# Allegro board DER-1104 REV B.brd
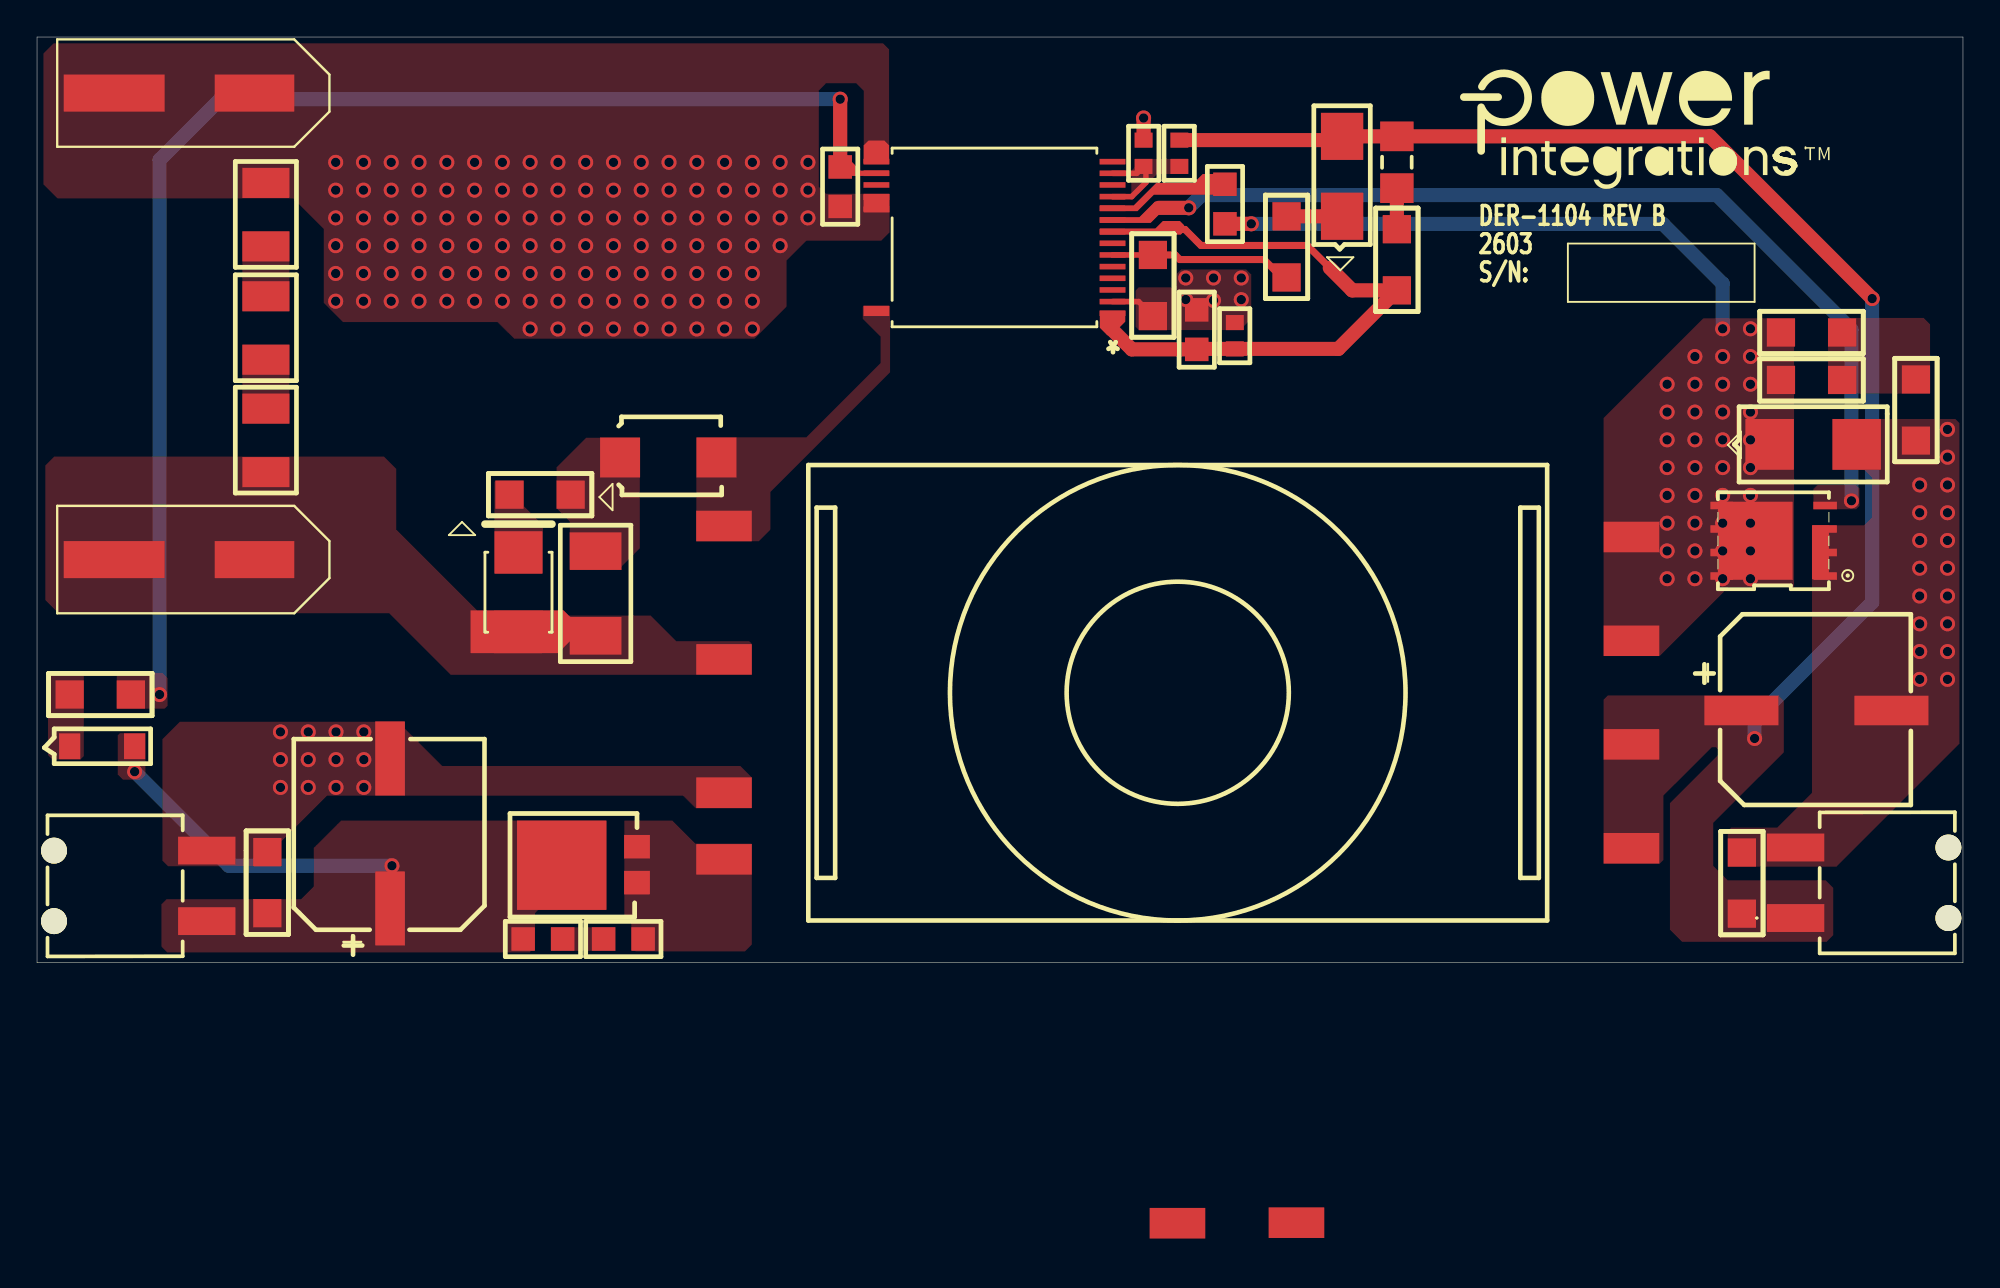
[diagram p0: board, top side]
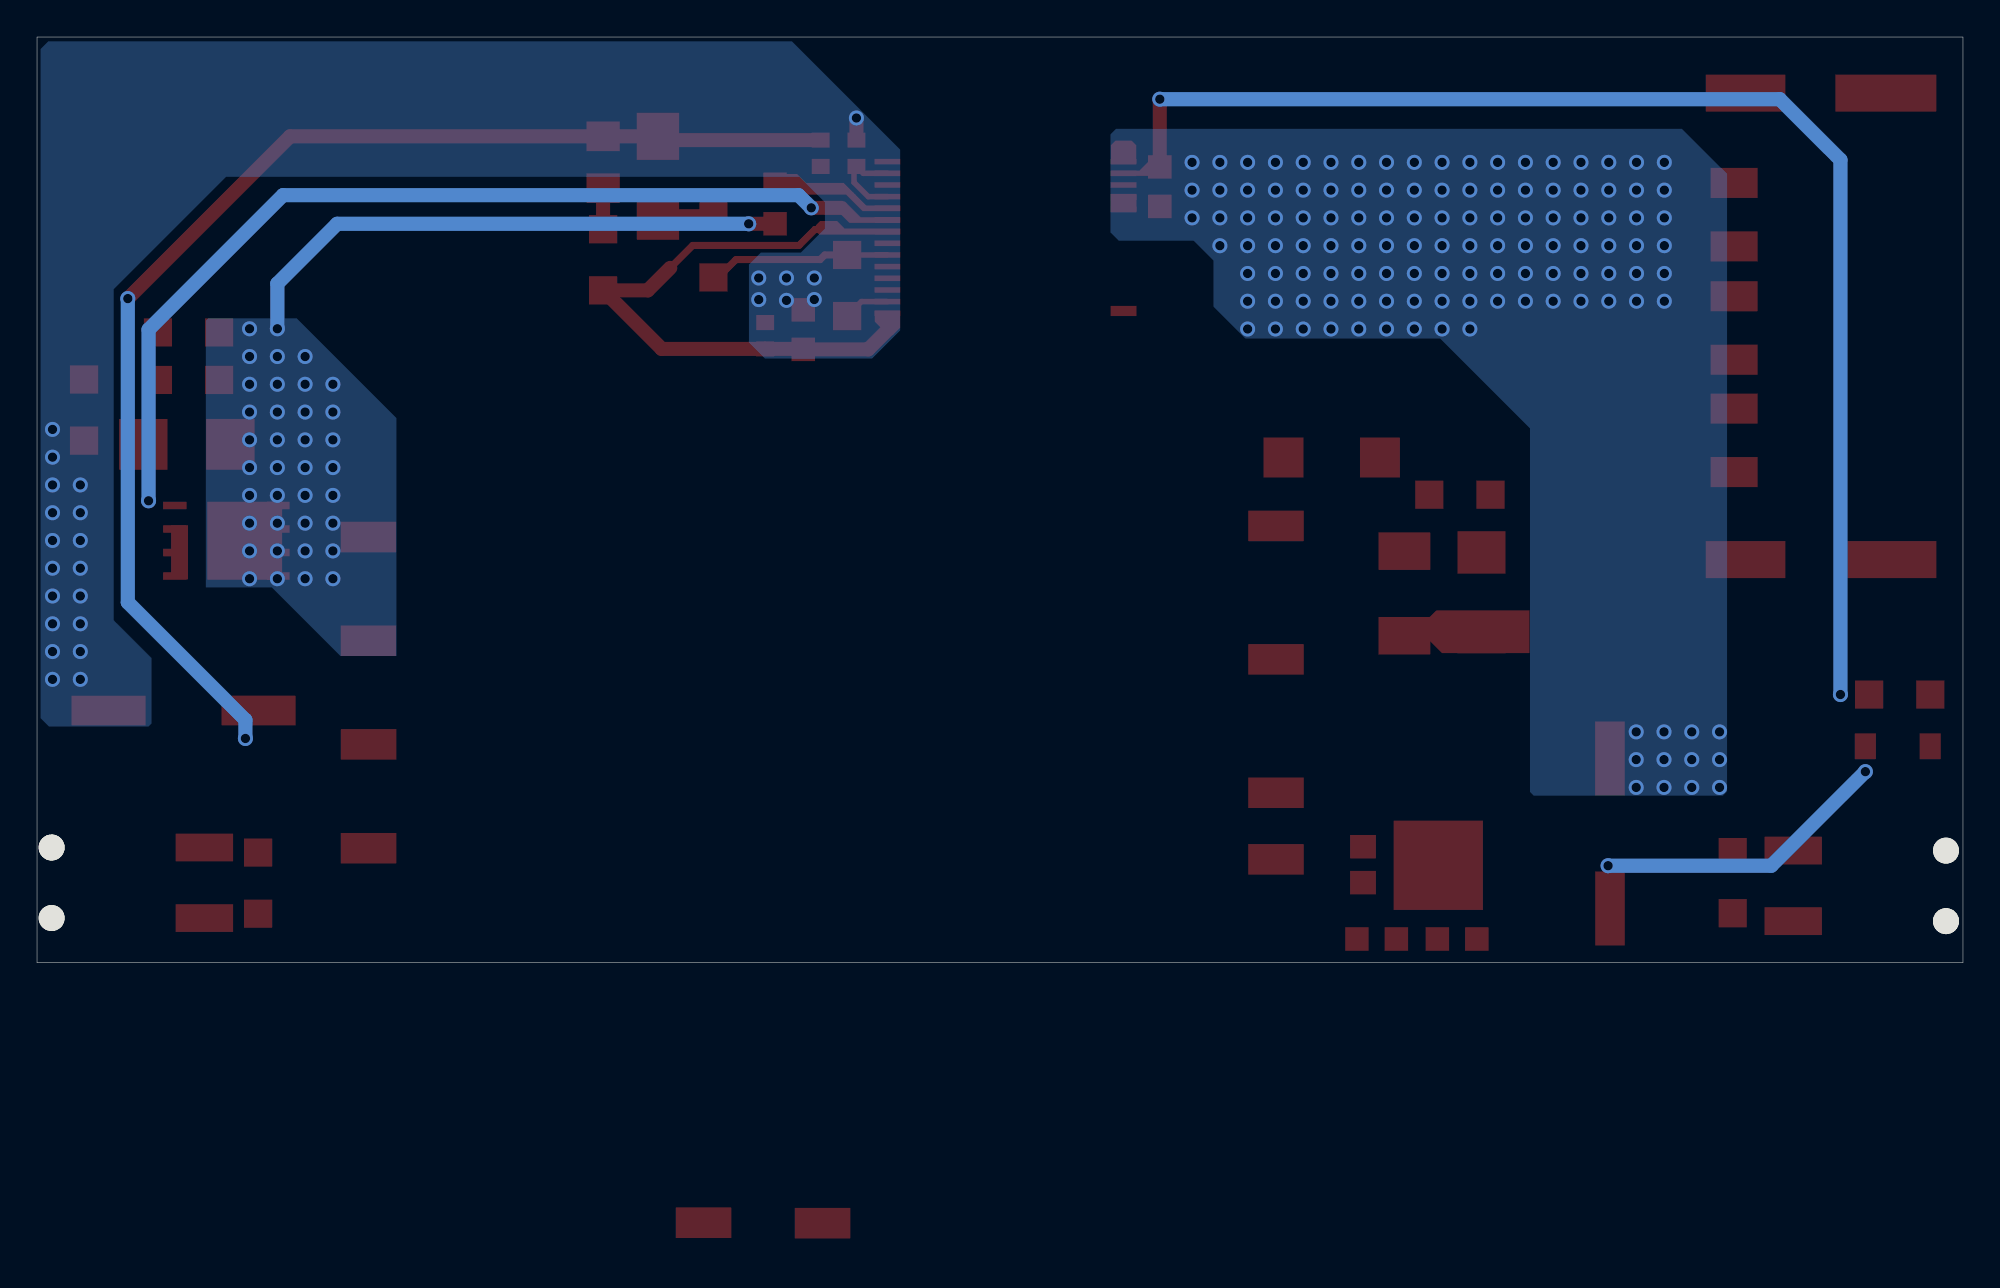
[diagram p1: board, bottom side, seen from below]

Outline 104 x 50 mm; copper layers: TOP, BOTTOM. Coordinates in mm from the lower left corner of the outline.
Outline path: 0,50 0,0 104,0 104,50 0,50

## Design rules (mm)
constraint set DEFAULT: min track width 0.508

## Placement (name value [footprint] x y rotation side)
C1  0.15 uF  [PISMC1210]  12.36 26.5 90 top
C2  0.15 uF  [PISMC1210]  12.36 32.57 90 top
C3  0.15 uF  [PISMC1210]  12.36 38.69 90 top
C4  4.7uF  [PISMC1206]  12.43 2.67 90 top
C5  220 uF  [PISMCPAN1VA]  19.06 2.93 90 top
C6  1000 pF  [PISMC0805]  28.38 1.28 180 top
C7  1 nF  [PISMC1808]  30.16 17.66 90 top
C8  470 nF  [PISMC0805]  43.37 42.98 270 top
C9  1 nF  [PISMC1206]  101.46 31.5 270 top
C10  4.7 uF  [PISMC1206]  60.26 34.93 90 top
C11  100 nF  [PISMC0603]  59.75 43.01 90 top
C12  470 pF  [PISMC0805]  62.62 35.26 270 top
C13  220 uF  [PISMCPAN1VA]  92.04 13.62 0 top
C14  4.7uF  [PISMC1206]  92.06 2.65 90 top
D1  BAV20W-TP  [PI_SM_SOD-123_12]  1.77 11.69 0 top
D2  V12P10-M3/86A  [PI_SM_D_TO-277A]  32.4 6.28 90 top
D3  S2Y  [PISMSMB]  31.48 27.29 0 top
D4  M2  [PISMDO214AC12]  70.47 40.32 90 top
NOREF  -  []  70.22 -95.6 0 top
NOREF#2  -  []  76.85 48.22 0 top
NOREF#3  -  []  0 0 90 top
NOREF#4  -  []  -224.6 -154.78 0 top
NOREF#5  -  []  0 0 0 top
Q1  AONS66520  [PISMPQFN5X6B]  96.56 20.89 90 top
R4  100 k  [PISMR1206]  28.82 25.28 180 top
R5  9.1  [PISMR0805]  32.73 1.28 180 top
R6  4.32 k  [PISMR1206]  5.07 14.49 180 top
R9  47.0  [PISMR0805]  64.15 39.91 90 top
R10  5.6  [PISMR1206]  94.17 31.48 0 top
R11  5.6  [PISMR1206]  94.17 34.04 0 top
R12  3.32 k  [PISMR0603]  64.68 34.58 270 top
R13  470  [RC1206]  73.43 43.24 270 top
R14  61.9 k  [PISMR1206]  73.43 39.62 270 top
R15  10  [PISMR0603]  61.68 44.43 270 top
R16  2.43 k  [PISMR1206]  67.48 37.02 90 top
T1  EIQ3001  [PISM_BOBBIN_EIQ3001]  61.6 14.58 0 top
U1  IMX2353F-H418  [INSOP-T28G_PWI]  51.7 39.17 180 top
UNK16V  CON2  [23839452]  9.17 6.06 270 top
UNK24V  CON2  [23839452]  94.96 2.41 90 top
VIN+  CON1F  [METZ_SM99S01VBNN00G7]  11.74 21.78 180 top
VIN-  CON1F  [METZ_SM99S01VBNN00G7]  11.74 46.97 180 top
VR1  SMBJ300CA  [DIO_DO214AA]  26 20.01 270 top
VR2  P6SMBJ110AS  [PISMDO214AA12]  93.56 28 0 top

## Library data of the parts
C1-C4 C7 C9 C10 C14 = CAP NP
C5 C13 = CAP POL
C6 C8 C12 = CAP NP: alternate symbols: (Unisem_RMCF0805UL)
C11 = CAP NP: alternate symbols: (Unisem_RMCF0603UL)
D1 D3 D4 = DIODE
D2 = DIODE SCHOTTKY_TO-277A
Q1 = FET_N_SGD_123_4_5678
R4 R6 R10 R11 R14 R16 = R
R5 R9 = R: alternate symbols: (Unisem_RMCF0805UL)
R12 R15 = R: alternate symbols: (Unisem_RMCF0603UL)
R13 = R: alternate symbols: (RC1206_HV)
T1 = BEIQ30_10P/GENERIC
U1 = InnoMux2-EP_InSOP-T28G
UNK16V UNK24V = CON2
VIN+ VIN- = IC_PIN_1Pin_2pad
VR1 = TVS_DIODE
VR2 = DIODE_ZENER

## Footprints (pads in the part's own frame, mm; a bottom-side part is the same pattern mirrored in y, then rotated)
23839452
  round 1.4 hole 1.4 unplated: (0,-8.25) (3.81,-8.25)
  rect 1.501x3.099 smd: 1(0,0) 2(3.81,0)
DIO_DO214AA
  rect 2.291x2.591 smd: 1(-2.149,0) 2(2.149,0)
INSOP-T28G_PWI
  rect 1.392x0.3 smd: 1(-6.375,4.094) 2(-6.375,3.465) 3(-6.375,2.835) 4(-6.375,2.205) 5(-6.375,1.575) 6(-6.375,0.945) 7(-6.375,0.315) 8(-6.375,-0.315) 9(-6.375,-0.945) 10(-6.375,-1.575) 11(-6.375,-2.205) 12(-6.375,-2.835) 13(-6.375,-3.465) 14(-6.375,-4.094) 15(6.375,-4.094) 16(6.375,-3.465) 17(6.375,-2.835) 18(6.375,-2.169) 19(6.375,-1.539)
  rect 1.392x0.551 smd: 28(6.375,3.97)
METZ_SM99S01VBNN00G7
  rect 4.3x1.999 smd: 1(0,0)
  rect 5.451x1.999 smd: 2(7.574,0)
PI_SM_D_TO-277A
  rect 1.27x1.397 smd: 1(-0.015,0) 2(-1.956,0)
  rect 4.826x4.826 smd: 3(-1.016,4.064)
PI_SM_SOD-123_12
  rect 1.143x1.397 smd: 1(0,0) 2(3.505,0)
PISM_BOBBIN_EIQ3001
  rect 3x1.651 smd: 1(-24.501,9.009) 2(-0.015,-28.651) 3(-24.501,1.801) 4(6.411,-28.623) 5(-24.501,-5.4) 6(-24.501,-8.999) 7(24.501,-8.4) 8(24.501,-2.789) 9(24.501,2.809) 10(24.501,8.41)
PISMC0603
  rect 0.813x0.965 smd: 1(0,0) 2(1.422,0)
PISMC0805
  rect 1.27x1.27 smd: 1(0,0) 2(2.134,0)
PISMC1206
  rect 1.524x1.524 smd: 1(0,0) 2(3.302,0)
PISMC1210
  rect 1.626x2.54 smd: 1(0,0) 2(3.429,0)
PISMC1808
  rect 2.032x2.794 smd: 1(0,0) 2(4.572,0)
PISMCPAN1VA
  rect 4x1.6 smd: 1(0,0) 2(8.1,0)
PISMDO214AA12
  rect 2.616x2.743 smd: 1(0,0) 2(4.699,0)
PISMDO214AC12
  rect 2.54x2.286 smd: 1(0,0) 2(4.318,0)
PISMPQFN5X6B
  rect 0.406x1.27 smd: 1(0,0) 2(1.27,0) 3(2.54,0) 4(3.81,0)
  rect 0.406x1.219 smd: 5(3.81,5.588) 6(2.54,5.588) 7(1.27,5.588) 8(0,5.588)
PISMR0603
  rect 0.813x0.965 smd: 1(0,0) 2(1.422,0)
PISMR0805
  rect 1.27x1.27 smd: 1(0,0) 2(2.134,0)
PISMR1206
  rect 1.524x1.524 smd: 1(0,0) 2(3.302,0)
PISMSMB
  rect 2.159x2.159 smd: 1(0,0) 2(5.207,0)
RC1206
  rect 1.6x1.801 smd: 1(-1.4,0) 2(1.4,0)

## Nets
GND POWER: C9.2 C10.1 C11.2 C12.1 C13.2 C14.2 Q1.1 Q1.2 Q1.3(S3) R12.1 U1.2 UNK24V.2 VR2.2
GND_SUPPLY: C3.2 C4.2 C5.2 C8.2 T1.5 U1.15 U1.18 U1.19 UNK16V.1 VIN-.1 VIN-.2
BPS: C10.2 R16.1 U1.6
SR: Q1.4 U1.9
TX16V+: D2.1 D2.2 R5.1 T1.6
TX24V+: C13.1 C14.1 D4.2 R13.1 R15.1 T1.7 T1.8 UNK24V.1
TXPRI+: C1.1 C7.1 T1.3 VIN+.1 VIN+.2 VR1.2
TXPRI-: D3.2 T1.1 U1.28
TXSR: Q1.5 Q1.6 Q1.7 Q1.8 R9.1 R10.1 R11.1 T1.9 T1.10 VR2.1
VCV1: C11.1 R15.2 U1.11 U1.13
N16959168: C12.2 R12.2 R14.2 U1.1 U1.8
N16971155: C4.1 C5.1 C6.2 D1.2 D2.3(CATHODE) UNK16V.2
N17016668: D1.1(K) R6.2
N17021924: C7.2 D3.1 R4.1
N17030469: C2.2 C3.1
N17037205: R13.2 R14.1
N17041030: R9.2 U1.10
N17051635: C8.1 R6.1 U1.16
N17059109: C6.1 R5.2
N17060192: R4.2 VR1.1(K)
N17061363: C1.2 C2.1
N17075641: C9.1 R10.2 R11.2
N17090457: D4.1 R16.2

Pads without a net: T1 2 4; U1 3 4 5 7 12 14 17

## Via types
v1: diameter 0.813, hole 0.508, TOP to BOTTOM, 195 vias

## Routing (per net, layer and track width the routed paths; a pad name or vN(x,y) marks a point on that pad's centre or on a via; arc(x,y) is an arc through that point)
GND POWER: length 3.7
  TOP w0.3: 60.26,34.93 59.48,35.71 U1.2
  TOP w0.762: C11.2 v1(59.75,45.63)
  vias: v1(62.03,36.98) v1(62.03,35.82) v1(63.53,36.98) v1(63.53,35.78) v1(65.03,36.98) v1(65.03,35.82) v1(101.66,25.81) v1(101.66,24.31) v1(101.66,22.81) v1(101.66,21.31) v1(101.66,19.81) v1(101.66,18.31) v1(101.66,16.81) v1(101.66,15.31) v1(103.16,28.81) v1(103.16,27.31) v1(103.16,25.81) v1(103.16,24.31) v1(103.16,22.81) v1(103.16,21.31) v1(103.16,19.81) v1(103.16,18.31) v1(103.16,16.81) v1(103.16,15.31)
GND_SUPPLY:
  vias: v1(13.14,12.47) v1(13.14,10.97) v1(13.14,9.47) v1(14.65,12.47) v1(14.65,10.97) v1(14.65,9.47) v1(16.13,43.23) v1(16.13,41.73) v1(16.13,40.23) v1(16.13,38.73) v1(16.13,37.23) v1(16.13,35.73) v1(16.14,12.47) v1(16.14,10.97) v1(16.14,9.47) v1(17.63,43.23) v1(17.63,41.73) v1(17.63,40.23) v1(17.63,38.73) v1(17.63,37.23) v1(17.63,35.73) v1(17.65,12.47) v1(17.65,10.97) v1(17.65,9.47) v1(19.13,43.23) v1(19.13,41.73) v1(19.13,40.23) v1(19.13,38.73) v1(19.13,37.23) v1(19.13,35.73) v1(20.63,43.23) v1(20.63,41.73) v1(20.63,40.23) v1(20.63,38.73) v1(20.63,37.23) v1(20.63,35.73) v1(22.13,43.23) v1(22.13,41.73) v1(22.13,40.23) v1(22.13,38.73) v1(22.13,37.23) v1(22.13,35.73) v1(23.63,43.23) v1(23.63,41.73) v1(23.63,40.23) v1(23.63,38.73) v1(23.63,37.23) v1(23.63,35.73) v1(25.13,43.23) v1(25.13,41.73) v1(25.13,40.23) v1(25.13,38.73) v1(25.13,37.23) v1(25.13,35.73) v1(26.63,43.23) v1(26.63,41.73) v1(26.63,40.23) v1(26.63,38.73) v1(26.63,37.23) v1(26.63,35.73) v1(26.63,34.23) v1(28.13,43.23) v1(28.13,41.73) v1(28.13,40.23) v1(28.13,38.73) v1(28.13,37.23) v1(28.13,35.73) v1(28.13,34.23) v1(29.63,43.23) v1(29.63,41.73) v1(29.63,40.23) v1(29.63,38.73) v1(29.63,37.23) v1(29.63,35.73) v1(29.63,34.23) v1(31.13,43.23) v1(31.13,41.73) v1(31.13,40.23) v1(31.13,38.73) v1(31.13,37.23) v1(31.13,35.73) v1(31.13,34.23) v1(32.63,43.23) v1(32.63,41.73) v1(32.63,40.23) v1(32.63,38.73) v1(32.63,37.23) v1(32.63,35.73) v1(32.63,34.23) v1(34.13,43.23) v1(34.13,41.73) v1(34.13,40.23) v1(34.13,38.73) v1(34.13,37.23) v1(34.13,35.73) v1(34.13,34.23) v1(35.63,43.23) v1(35.63,41.73) v1(35.63,40.23) v1(35.63,38.73) v1(35.63,37.23) v1(35.63,35.73) v1(35.63,34.23) v1(37.13,43.23) v1(37.13,41.73) v1(37.13,40.23) v1(37.13,38.73) v1(37.13,37.23) v1(37.13,35.73) v1(37.13,34.23) v1(38.63,43.23) v1(38.63,41.73) v1(38.63,40.23) v1(38.63,38.73) v1(38.63,37.23) v1(38.63,35.73) v1(38.63,34.23) v1(40.13,43.23) v1(40.13,41.73) v1(40.13,40.23) v1(40.13,38.73) v1(41.63,43.23) v1(41.63,41.73) v1(41.63,40.23)
BPS: length 9.9
  TOP w0.3: 60.26,38.23 C10.2 U1.6
  TOP w0.381: C10.2 61.46,38.23 61.71,37.98 66.26,37.98 67.22,37.02 R16.1
SR: length 49.9
  TOP w0.762: v1(62.19,40.77) 60.59,40.77
  BOTTOM w0.762: v1(97.98,24.95) 97.98,34.2 90.72,41.46 62.88,41.46 v1(62.19,40.77)
TX24V+: length 67.5
  TOP w0.762: R15.1 70.27,44.43 D4.2 R13.1 90.34,44.64 v1(99.1,35.87)
  BOTTOM w0.762: v1(92.75,12.11) 92.75,13.11 99.1,19.46 v1(99.1,35.87)
TXSR: length 30.7
  TOP w0.762: R9.1 v1(65.57,39.91)
  BOTTOM w0.762: v1(91.02,34.24) 91.02,36.68 87.8,39.91 v1(65.57,39.91)
  vias: v1(88.02,31.24) v1(88.02,29.74) v1(88.02,28.24) v1(88.02,26.74) v1(88.02,25.24) v1(88.02,23.74) v1(88.02,22.24) v1(88.02,20.74) v1(89.52,32.74) v1(89.52,31.24) v1(89.52,29.74) v1(89.52,28.24) v1(89.52,26.74) v1(89.52,25.24) v1(89.52,23.74) v1(89.52,22.24) v1(89.52,20.74) v1(91.02,32.74) v1(91.02,31.24) v1(91.02,29.74) v1(91.02,28.24) v1(91.02,26.74) v1(91.02,25.24) v1(91.02,23.74) v1(91.02,22.24) v1(91.02,20.74) v1(92.52,34.24) v1(92.52,32.74) v1(92.52,31.24) v1(92.52,29.74) v1(92.52,28.24) v1(92.52,26.74) v1(92.52,25.24) v1(92.52,23.74) v1(92.52,22.24) v1(92.52,20.74)
VCV1: length 4.9
  TOP w0.3: U1.11 59.11,41.38 59.88,42.15 59.88,42.88 C11.1 59.38,42.64 U1.13
N16959168: length 31.1
  TOP w0.381: 60.77,39.61 61.99,39.61 62.85,38.74 68.59,38.74 69.81,37.53
  TOP w0.762: 58.08,34.17 59.12,33.13 C12.2 62.65,33.15 R12.2 70.27,33.15 R14.2 71.02,36.32 69.81,37.53
N16971155: length 16
  BOTTOM w0.762: v1(19.16,5.24) 10.35,5.24 v1(5.27,10.32)
N17037205: length 2.2
  TOP w0.762: R14.1 R13.2
N17051635: length 70.6
  TOP w0.762: v1(43.37,46.64) C8.1
  BOTTOM w0.762: v1(6.62,14.49) 6.62,43.37 9.89,46.64 v1(43.37,46.64)
N17090457: length 3
  TOP w0.762: D4.1 R16.2

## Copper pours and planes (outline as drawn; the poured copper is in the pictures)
GND POWER on TOP (solid shape): 96.76,20.71 95.85,20.71 95.85,23.63 96.76,23.63
GND POWER on TOP: 64.96,34.17 65.57,34.78 65.57,37.17 65.29,37.45 61.79,37.45 61.56,37.22 61.56,36.58 61.46,36.48 59.5,36.48 59.32,36.3 59.32,34.35 59.5,34.17
GND POWER on TOP: 95.87,23.63 98.67,23.63 99.1,24.06 99.1,26.2 98.64,26.65 97.19,26.65 96.96,26.88 96.96,29.14 97.19,29.37 103.59,29.37 103.81,29.15 103.81,11.83 97.17,5.19 91.3,5.19 91.3,7.12 91.48,7.3 93.97,7.3 95.85,9.18 95.85,23.6
GND POWER on BOTTOM: 64.69,32.63 58.9,32.63 57.39,34.15 57.39,43.92 63.23,49.77 103.39,49.77 103.81,49.35 103.81,13.22 103.35,12.76 97.98,12.76 97.82,12.92 97.82,16.45 99.86,18.5 99.86,36.38 93.79,42.45 62.83,42.45 61.46,41.08 61.46,39.66 62.75,38.36 64.91,38.36 65.56,37.71 65.56,33.5
GND_SUPPLY on TOP (solid shape): 46.03,40.53 44.63,40.53 44.63,41.53 46.03,41.53
GND_SUPPLY on TOP (solid shape): 46.01,44.15 46.01,43.14 44.69,43.14 44.64,43.19 44.64,44.15 44.89,44.41 45.76,44.41
GND_SUPPLY on TOP: 0.34,42.04 0.34,49.11 0.9,49.66 45.68,49.66 46.01,49.33 46.01,43.19 45.96,43.14 44.69,43.14 44.64,43.19 44.64,47.1 44.23,47.51 42.61,47.51 42.21,47.11 42.21,41.92 42.6,41.54 46.01,41.54 46.04,41.51 46.04,39.45 45.58,39 41.54,39 40.47,37.93 40.47,35.44 38.74,33.71 25.76,33.71 24.87,34.6 16.52,34.6 15.48,35.64 15.48,39.63 13.83,41.28 1.1,41.28
GND_SUPPLY on TOP: 34.89,9.02 35.57,8.34 38.6,8.34 38.6,10.02 37.99,10.62 21.88,10.62 19.85,12.66 19.85,13.01 7.71,13.01 6.77,12.07 6.77,5.52 7.07,5.21 13.2,5.21 13.2,6.56 15.66,9.02
GND_SUPPLY on BOTTOM: 45.73,45.04 46.04,44.74 46.04,39.45 45.58,39 41.54,39 40.47,37.93 40.47,35.44 38.75,33.71 28.23,33.71 23.38,28.86 23.38,9.23 23.18,9.02 12.97,9.02 12.74,9.25 12.74,42.6 15.18,45.04
SR on TOP (solid shape): 60.77,40.93 60.77,40.6 60.13,39.96 57.39,39.96 57.39,40.27 59.52,40.27 60.36,41.1 60.59,41.1
SR on TOP: 95.92,24.49 98.23,24.49 98.41,24.67 98.41,25.61 98.21,25.81 96.15,25.81 95.92,25.59
TX16V+ on TOP: 38.6,6.43 35.55,6.43 34.3,7.68 31.71,7.68 31.71,2.5 32.09,2.12 32.09,0.85 32.32,0.62 38.24,0.62 38.6,0.97
TX24V+ on TOP: 84.59,5.34 84.59,14.21 84.82,14.43 94.04,14.43 94.32,14.16 94.32,11.36 90.51,7.55 90.51,5.24 91.3,4.45 96.58,4.45 96.99,4.05 96.99,1.48 96.63,1.13 88.84,1.13 88.18,1.79 88.18,8.62 90.82,11.26 90.82,11.49 90.67,11.64 90.44,11.64 87.82,9.02 87.82,5.54 87.62,5.34
TXPRI+ on TOP (solid shape): 28.82,18.65 28.82,17.41 28.13,16.72 23.43,16.72 23.41,16.75 23.41,19.03 28.44,19.03
TXPRI+ on TOP: 1.16,18.88 0.44,19.59 0.44,26.86 0.93,27.34 18.73,27.34 19.39,26.68 19.39,23.4 24.04,18.75 24.04,18.02 24.19,17.86 27.83,17.86 28.71,18.75 33.13,18.75 34.52,17.37 38.46,17.37 38.6,17.23 38.6,15.55 22.34,15.55 19.01,18.88
TXPRI- on TOP: 35.6,28.38 35.6,22.77 38.98,22.77 39.6,23.39 39.6,25.42 46.06,31.88 46.06,35.44 46.01,35.49 44.64,35.49 44.59,35.44 44.59,34.78 45.55,33.82 45.55,32.39 41.54,28.38
TXSR on TOP (solid shape): 94.81,20.68 90.77,20.68 90.77,24.9 94.81,24.9
TXSR on TOP: 94.88,20.28 94.88,34.5 94.58,34.81 89.98,34.81 84.59,29.42 84.59,16.57 87.62,16.57 91.33,20.28
TXSR on BOTTOM: 94.88,20.28 94.88,34.68 94.75,34.81 89.98,34.81 84.59,29.42 84.59,16.57 87.62,16.57 91.33,20.28
VCV1 on TOP: 62.17,43.42 59.27,43.42 59.27,42.96 59.09,42.78 59.09,41.36 59.25,41.36 60.49,42.6 62.17,42.6
N16959168 on TOP (solid shape): 58.76,34.63 58.03,33.89 57.8,33.89 57.39,34.3 57.39,35.21 58.76,35.21
N16959168 on TOP (solid shape): 61.94,39.83 61.94,39.5 61.76,39.33 57.39,39.33 57.39,39.66 60.39,39.66 60.79,40.06 61.71,40.06
N16971155 on TOP: 5.85,12.4 4.48,12.4 4.36,12.28 4.36,10.17 4.64,9.89 5.6,9.89 5.85,10.14
N16971155 on TOP: 14.95,6.21 14.95,4.12 14.26,3.44 7,3.44 6.72,3.16 6.72,0.87 7.04,0.55 26.59,0.55 26.89,0.85 26.89,2.67 27.09,2.88 30.49,2.88 30.72,3.11 30.72,7.55 30.59,7.68 16.42,7.68
N17016668 on TOP: 2.53,11.16 2.35,10.98 0.83,10.98 0.6,11.21 0.6,15.37 0.88,15.65 2.4,15.65 2.53,15.53
N17021924 on TOP: 32.35,28.35 29.65,28.35 28.05,26.75 28.05,24.54 28.77,23.83 28.77,21.57 29.1,21.24 31.41,21.24 32.55,22.39 32.55,28.15
N17030469 on TOP: 11.09,39.5 13.63,39.5 13.63,35.19 11.09,35.19
N17041030 on TOP (solid shape): 64.73,42.45 64.73,41.61 64.6,41.49 60.31,41.49 59.42,40.6 57.39,40.6 57.39,40.9 59.22,40.9 60.44,42.12 62.47,42.12 62.95,42.6 64.58,42.6
N17051635 on TOP (solid shape): 44.48,42.78 46.01,42.78 46.01,42.5 43.22,42.5 42.96,42.76 42.96,43.42 43.07,43.52 43.74,43.52
N17051635 on TOP: 7.05,13.88 6.9,13.72 4.31,13.72 4.31,15.55 4.41,15.65 6.77,15.65 7.05,15.37
N17059109 on TOP: 31.23,1.92 27.75,1.92 27.75,0.65 31.23,0.65
N17060192 on TOP: 27.32,23.63 27.32,21.04 24.8,21.04 24.7,21.14 24.7,25.97 24.78,26.04 26.17,26.04 26.25,25.97 26.25,24.7
N17061363 on TOP: 11.09,33.38 13.63,33.38 13.63,29.12 11.09,29.12
N17075641 on TOP: 96.86,34.83 101.87,34.83 102.22,34.48 102.22,30.97 101.99,30.74 96.84,30.74 96.71,30.87 96.71,34.68

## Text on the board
Ref Des/Silkscreen Top: DER-1104 REV B | 2603 | S/N:
User.5: 3X UNPLATED SLOT
User.8: FIGURE | FINISHED_SIZE | 20.0 | 55.098 | DRILL CHART: TOP to BOTTOM | ALL UNITS ARE IN MILS | TOLERANCE_DRILL | +3.0/-3.0 | PLATED | NON-PLATED | QTY | 195 | 4 | 199 | TOTAL HOLES:
